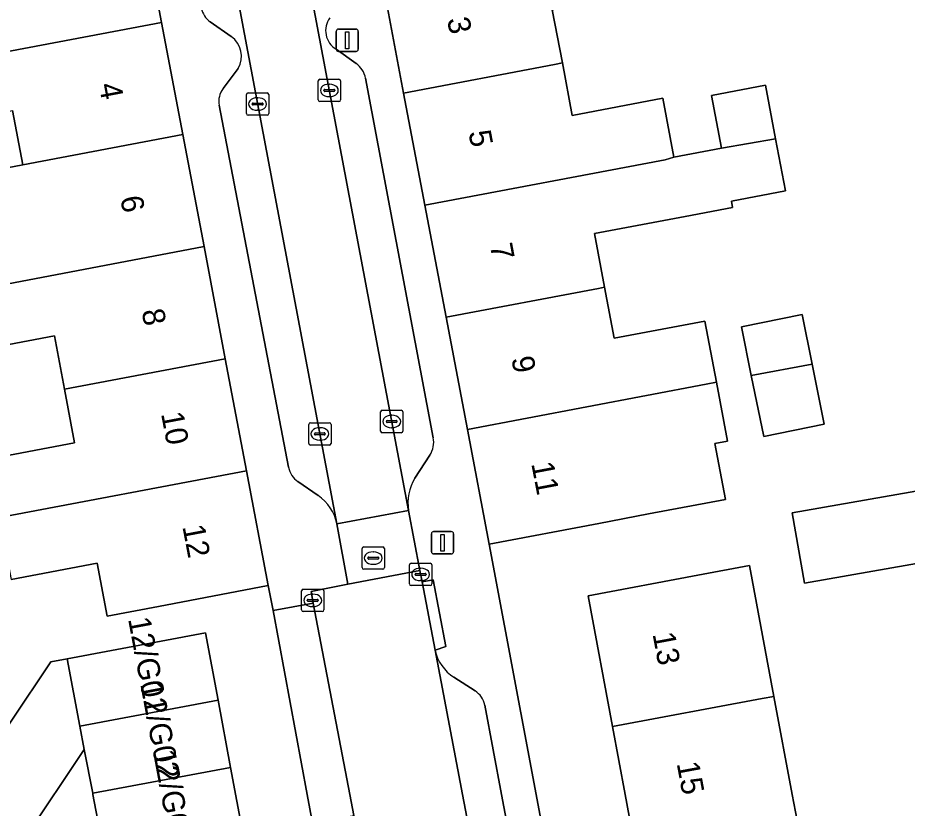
# Model space of a CAD drawing. Extents: x 158352 to 159489, y 383828 to 384603.
# Drawn here: x 158799.12 to 158838.9, y 383999.38 to 384034.72 of the extents above; entities that cross this region are included whole.
import ezdxf

# ---------------------------------------------------------------- set-up
doc = ezdxf.new("R2010")
doc.units = 0
for name, color, linetype in [('IMGEO_Erf', 7, 'Continuous'), ('IMGEO_Kolk', 7, 'Continuous'), ('IMGEO_Lichtmast', 7, 'Continuous'), ('IMGEO_Pand', 7, 'Continuous'), ('IMGEO_Pand_nummerreeks', 7, 'Continuous'), ('IMGEO_Parkeervlak_open', 7, 'Continuous'), ('IMGEO_Rijbaan_lokaal_open', 7, 'Continuous'), ('IMGEO_Rioolput', 7, 'Continuous'), ('IMGEO_Voetpad_open', 7, 'Continuous')]:
    doc.layers.add(name, color=color, linetype=linetype)

msp = doc.modelspace()

# ---------------------------------------------------------------- linework, layer by layer
at = {"layer": 'IMGEO_Erf'}
for points in [[(158823.028, 384035.085), (158823.479, 384032.704), (158823.923, 384030.362), (158827.97, 384031.129), (158828.471, 384028.487), (158830.594, 384028.89), (158830.147, 384031.248), (158832.566, 384031.706), (158833.019, 384029.317), (158833.46, 384026.99), (158831.041, 384026.532), (158831.095, 384026.248), (158828.971, 384025.846), (158824.912, 384025.077), (158825.368, 384022.673), (158825.799, 384020.396), (158829.85, 384021.163), (158830.369, 384018.427), (158830.867, 384015.798), (158830.3, 384015.691), (158830.774, 384013.189), (158827.339, 384012.538), (158825.116, 384012.116), (158820.203, 384011.185), (158822.303, 384000), (158825.129, 383984.951)], [(158796.223, 384027.56), (158799.352, 384028.152), (158798.893, 384030.579)], [(158797.802, 384014.988), (158801.665, 384015.719), (158801.211, 384018.118), (158800.76, 384020.506), (158796.907, 384019.777)], [(158812.308, 383998.709), (158812.069, 384000), (158810.545, 384008.215), (158810.321, 384009.334), (158805.409, 384008.405), (158803.118, 384007.971), (158802.67, 384010.332), (158798.821, 384009.603)], [(158826.753, 383997.491), (158826.285, 384000), (158825.719, 384003.034), (158824.629, 384008.882), (158829.545, 384009.799), (158831.854, 384010.229), (158832.942, 384004.38), (158833.757, 384000), (158833.974, 383998.837)], [(158795.269, 383997.968), (158800.605, 384005.927), (158801.324, 384006.061), (158807.522, 384007.216), (158808.082, 384004.205), (158808.642, 384001.195), (158809.202, 383998.184)], [(158803.048, 383997.036), (158802.482, 384000), (158802.473, 384000.047), (158802.097, 384002.012), (158799.476, 383998.101)]]:
    msp.add_lwpolyline(points, dxfattribs=at)
for points in [[(158834.649, 384019.239), (158835.196, 384016.556), (158832.485, 384016.003), (158831.93, 384018.723), (158831.486, 384020.901), (158834.198, 384021.454)], [(158845.956, 384014.73), (158846.506, 384011.58), (158841.025, 384010.622), (158834.309, 384009.447), (158833.758, 384012.596), (158840.474, 384013.771)]]:
    msp.add_lwpolyline(points, close=True, dxfattribs=at)
at = {"layer": 'IMGEO_Kolk'}
for p, q in [((158812.557, 384031.052), (158812.557, 384031.904)), ((158812.632, 384031.978), (158813.484, 384031.978)), ((158813.045, 384031.758), (158813.07, 384031.758)), ((158813.558, 384031.904), (158813.558, 384031.052)), ((158809.349, 384030.443), (158809.349, 384031.295)), ((158809.424, 384031.369), (158810.276, 384031.369)), ((158810.35, 384031.295), (158810.35, 384030.443)), ((158812.816, 384031.472), (158812.816, 384031.484)), ((158813.254, 384031.435), (158812.856, 384031.435)), ((158812.859, 384031.521), (158813.257, 384031.521)), ((158813.3, 384031.484), (158813.3, 384031.472)), ((158809.608, 384030.863), (158809.608, 384030.875)), ((158809.651, 384030.912), (158810.049, 384030.912)), ((158809.837, 384031.149), (158809.862, 384031.149)), ((158810.092, 384030.875), (158810.092, 384030.863)), ((158813.484, 384030.978), (158812.632, 384030.978)), ((158813.068, 384031.198), (158813.043, 384031.198)), ((158810.046, 384030.826), (158809.648, 384030.826)), ((158809.86, 384030.589), (158809.835, 384030.589)), ((158810.276, 384030.369), (158809.424, 384030.369)), ((158815.346, 384016.247), (158815.346, 384017.099)), ((158815.421, 384017.173), (158816.273, 384017.173)), ((158815.834, 384016.953), (158815.859, 384016.953)), ((158816.347, 384017.099), (158816.347, 384016.247)), ((158812.133, 384015.691), (158812.133, 384016.543)), ((158812.208, 384016.617), (158813.06, 384016.617)), ((158813.134, 384016.543), (158813.134, 384015.691)), ((158815.605, 384016.667), (158815.605, 384016.679)), ((158816.043, 384016.63), (158815.645, 384016.63)), ((158815.648, 384016.716), (158816.046, 384016.716)), ((158816.089, 384016.679), (158816.089, 384016.667)), ((158812.392, 384016.111), (158812.392, 384016.123)), ((158812.435, 384016.16), (158812.833, 384016.16)), ((158812.621, 384016.397), (158812.646, 384016.397)), ((158812.876, 384016.123), (158812.876, 384016.111)), ((158816.273, 384016.173), (158815.421, 384016.173)), ((158815.857, 384016.393), (158815.832, 384016.393)), ((158812.83, 384016.074), (158812.432, 384016.074)), ((158812.644, 384015.837), (158812.619, 384015.837)), ((158813.06, 384015.617), (158812.208, 384015.617)), ((158816.64, 384009.41), (158816.64, 384010.262)), ((158816.715, 384010.336), (158817.567, 384010.336)), ((158817.641, 384010.262), (158817.641, 384009.41)), ((158816.899, 384009.83), (158816.899, 384009.842)), ((158817.337, 384009.793), (158816.939, 384009.793)), ((158816.942, 384009.879), (158817.34, 384009.879)), ((158817.128, 384010.116), (158817.153, 384010.116)), ((158817.383, 384009.842), (158817.383, 384009.83)), ((158817.151, 384009.556), (158817.126, 384009.556)), ((158811.812, 384008.248), (158811.812, 384009.1)), ((158811.887, 384009.174), (158812.739, 384009.174)), ((158812.813, 384009.1), (158812.813, 384008.248)), ((158817.567, 384009.336), (158816.715, 384009.336)), ((158812.071, 384008.668), (158812.071, 384008.68)), ((158812.509, 384008.631), (158812.111, 384008.631)), ((158812.114, 384008.717), (158812.512, 384008.717)), ((158812.3, 384008.954), (158812.325, 384008.954)), ((158812.555, 384008.68), (158812.555, 384008.668)), ((158812.739, 384008.174), (158811.887, 384008.174)), ((158812.323, 384008.394), (158812.298, 384008.394))]:
    msp.add_line(p, q, dxfattribs=at)
for points in [[(158812.557, 384031.052), (158812.557, 384031.904)], [(158812.632, 384031.978), (158813.484, 384031.978)], [(158813.558, 384031.904), (158813.558, 384031.052)], [(158809.349, 384030.443), (158809.349, 384031.295)], [(158809.424, 384031.369), (158810.276, 384031.369)], [(158810.35, 384031.295), (158810.35, 384030.443)], [(158813.484, 384030.978), (158812.632, 384030.978)], [(158810.276, 384030.369), (158809.424, 384030.369)], [(158815.346, 384016.247), (158815.346, 384017.099)], [(158815.421, 384017.173), (158816.273, 384017.173)], [(158816.347, 384017.099), (158816.347, 384016.247)], [(158812.133, 384015.691), (158812.133, 384016.543)], [(158812.208, 384016.617), (158813.06, 384016.617)], [(158813.134, 384016.543), (158813.134, 384015.691)], [(158816.273, 384016.173), (158815.421, 384016.173)], [(158813.06, 384015.617), (158812.208, 384015.617)], [(158816.64, 384009.41), (158816.64, 384010.262)], [(158816.715, 384010.336), (158817.567, 384010.336)], [(158817.641, 384010.262), (158817.641, 384009.41)], [(158811.812, 384008.248), (158811.812, 384009.1)], [(158811.887, 384009.174), (158812.739, 384009.174)], [(158812.813, 384009.1), (158812.813, 384008.248)], [(158817.567, 384009.336), (158816.715, 384009.336)], [(158812.739, 384008.174), (158811.887, 384008.174)]]:
    msp.add_lwpolyline(points, dxfattribs=at)
for centre, radius, start, end in [((158812.634, 384031.902), 0.0765, 91.552, 178.448), ((158812.634, 384031.902), 0.0765, 91.552, 178.448), ((158813.482, 384031.902), 0.0765, 1.552, 88.448), ((158813.482, 384031.902), 0.0765, 1.552, 88.448), ((158809.426, 384031.293), 0.0765, 91.552, 178.448), ((158809.426, 384031.293), 0.0765, 91.552, 178.448), ((158810.274, 384031.293), 0.0765, 1.552, 88.448), ((158810.274, 384031.293), 0.0765, 1.552, 88.448), ((158812.856, 384031.481), 0.0403, 85.8775, 175.7526), ((158812.853, 384031.471), 0.0366, 178.938, 274.7102), ((158813.257, 384031.478), 0.043, 264.8664, 352.4533), ((158813.261, 384031.483), 0.0386, 1.7309, 96.639), ((158809.648, 384030.872), 0.0403, 85.8775, 175.7526), ((158809.645, 384030.862), 0.0366, 178.938, 274.7102), ((158810.049, 384030.869), 0.043, 264.8664, 352.4533), ((158810.053, 384030.874), 0.0386, 1.7309, 96.639), ((158812.634, 384031.054), 0.0765, 181.552, 268.448), ((158812.634, 384031.054), 0.0765, 181.552, 268.448), ((158813.482, 384031.054), 0.0765, 271.552, 358.448), ((158813.482, 384031.054), 0.0765, 271.552, 358.448), ((158809.426, 384030.445), 0.0765, 181.552, 268.448), ((158809.426, 384030.445), 0.0765, 181.552, 268.448), ((158810.274, 384030.445), 0.0765, 271.552, 358.448), ((158810.274, 384030.445), 0.0765, 271.552, 358.448), ((158815.423, 384017.097), 0.0765, 91.552, 178.448), ((158815.423, 384017.097), 0.0765, 91.552, 178.448), ((158816.271, 384017.097), 0.0765, 1.552, 88.448), ((158816.271, 384017.097), 0.0765, 1.552, 88.448), ((158812.21, 384016.541), 0.0765, 91.552, 178.448), ((158812.21, 384016.541), 0.0765, 91.552, 178.448), ((158813.058, 384016.541), 0.0765, 1.552, 88.448), ((158813.058, 384016.541), 0.0765, 1.552, 88.448), ((158815.645, 384016.676), 0.0403, 85.8775, 175.7526), ((158815.642, 384016.666), 0.0366, 178.938, 274.7102), ((158816.046, 384016.673), 0.043, 264.8664, 352.4533), ((158816.05, 384016.678), 0.0386, 1.7309, 96.639), ((158812.432, 384016.12), 0.0403, 85.8775, 175.7526), ((158812.837, 384016.122), 0.0386, 1.7309, 96.639), ((158815.423, 384016.249), 0.0765, 181.552, 268.448), ((158815.423, 384016.249), 0.0765, 181.552, 268.448), ((158816.271, 384016.249), 0.0765, 271.552, 358.448), ((158816.271, 384016.249), 0.0765, 271.552, 358.448), ((158812.429, 384016.11), 0.0366, 178.938, 274.7102), ((158812.833, 384016.117), 0.043, 264.8664, 352.4533), ((158812.21, 384015.693), 0.0765, 181.552, 268.448), ((158812.21, 384015.693), 0.0765, 181.552, 268.448), ((158813.058, 384015.693), 0.0765, 271.552, 358.448), ((158813.058, 384015.693), 0.0765, 271.552, 358.448), ((158816.717, 384010.26), 0.0765, 91.552, 178.448), ((158816.717, 384010.26), 0.0765, 91.552, 178.448), ((158817.565, 384010.26), 0.0765, 1.552, 88.448), ((158817.565, 384010.26), 0.0765, 1.552, 88.448), ((158816.939, 384009.839), 0.0403, 85.8775, 175.7526), ((158816.936, 384009.829), 0.0366, 178.938, 274.7102), ((158817.34, 384009.836), 0.043, 264.8664, 352.4533), ((158817.344, 384009.841), 0.0386, 1.7309, 96.639), ((158816.717, 384009.412), 0.0765, 181.552, 268.448), ((158816.717, 384009.412), 0.0765, 181.552, 268.448), ((158817.565, 384009.412), 0.0765, 271.552, 358.448), ((158817.565, 384009.412), 0.0765, 271.552, 358.448), ((158811.889, 384009.098), 0.0765, 91.552, 178.448), ((158811.889, 384009.098), 0.0765, 91.552, 178.448), ((158812.737, 384009.098), 0.0765, 1.552, 88.448), ((158812.737, 384009.098), 0.0765, 1.552, 88.448), ((158812.111, 384008.677), 0.0403, 85.8775, 175.7526), ((158812.108, 384008.667), 0.0366, 178.938, 274.7102), ((158812.512, 384008.674), 0.043, 264.8664, 352.4533), ((158812.516, 384008.679), 0.0386, 1.7309, 96.639), ((158811.889, 384008.25), 0.0765, 181.552, 268.448), ((158811.889, 384008.25), 0.0765, 181.552, 268.448), ((158812.737, 384008.25), 0.0765, 271.552, 358.448), ((158812.737, 384008.25), 0.0765, 271.552, 358.448)]:
    msp.add_arc(centre, radius, start, end, dxfattribs=at)
for centre, major_axis, ratio, start_param, end_param in [((158813.044, 384031.478), (-0.387, 0.002), 0.722429, 4.712389, 7.853982), ((158813.069, 384031.478), (-0.39, 0.002), 0.717154, 1.570796, 4.712389), ((158809.836, 384030.869), (-0.387, 0.002), 0.722429, 4.712389, 7.853982), ((158809.861, 384030.869), (-0.39, 0.002), 0.717154, 1.570796, 4.712389), ((158815.833, 384016.673), (-0.387, 0.002), 0.722429, 4.712389, 7.853982), ((158815.858, 384016.673), (-0.39, 0.002), 0.717154, 1.570796, 4.712389), ((158812.62, 384016.117), (-0.387, 0.002), 0.722429, 4.712389, 7.853982), ((158812.645, 384016.117), (-0.39, 0.002), 0.717154, 1.570796, 4.712389), ((158817.127, 384009.836), (-0.387, 0.002), 0.722429, 4.712389, 7.853982), ((158817.152, 384009.836), (-0.39, 0.002), 0.717154, 1.570796, 4.712389), ((158812.299, 384008.674), (-0.387, 0.002), 0.722429, 4.712389, 7.853982), ((158812.324, 384008.674), (-0.39, 0.002), 0.717154, 1.570796, 4.712389)]:
    msp.add_ellipse(centre, major_axis=major_axis, ratio=ratio, start_param=start_param, end_param=end_param, dxfattribs=at)
at = {"layer": 'IMGEO_Lichtmast'}
for p, q in [((158813.363, 384033.319), (158813.363, 384034.119)), ((158813.363, 384034.119), (158813.363, 384033.319)), ((158813.463, 384034.219), (158814.253, 384034.219)), ((158814.253, 384034.219), (158813.463, 384034.219)), ((158814.353, 384034.119), (158814.353, 384033.319)), ((158814.353, 384033.319), (158814.353, 384034.119)), ((158814.253, 384033.219), (158813.463, 384033.219)), ((158813.463, 384033.219), (158814.253, 384033.219)), ((158817.721, 384011.749), (158818.511, 384011.749)), ((158818.511, 384011.749), (158817.721, 384011.749)), ((158817.621, 384010.849), (158817.621, 384011.649)), ((158817.621, 384011.649), (158817.621, 384010.849)), ((158818.611, 384011.649), (158818.611, 384010.849)), ((158818.611, 384010.849), (158818.611, 384011.649)), ((158818.511, 384010.749), (158817.721, 384010.749)), ((158817.721, 384010.749), (158818.511, 384010.749))]:
    msp.add_line(p, q, dxfattribs=at)
for points in [[(158813.783, 384034.094), (158813.933, 384034.094), (158813.933, 384033.344), (158813.783, 384033.344), (158813.783, 384034.094)], [(158818.041, 384011.624), (158818.191, 384011.624), (158818.191, 384010.874), (158818.041, 384010.874), (158818.041, 384011.624)]]:
    msp.add_lwpolyline(points, dxfattribs=at)
for centre, start, end in [((158813.463, 384034.119), 90, 180), ((158813.463, 384034.119), 90, 180), ((158814.253, 384034.119), 0, 90), ((158814.253, 384034.119), 360, 90), ((158813.463, 384033.319), 180, 270), ((158813.463, 384033.319), 180, 270), ((158814.253, 384033.319), 270, 0), ((158814.253, 384033.319), 270, 0), ((158817.721, 384011.649), 90, 180), ((158817.721, 384011.649), 90, 180), ((158818.511, 384011.649), 0, 90), ((158818.511, 384011.649), 360, 90), ((158817.721, 384010.849), 180, 270), ((158817.721, 384010.849), 180, 270), ((158818.511, 384010.849), 270, 0), ((158818.511, 384010.849), 270, 0)]:
    msp.add_arc(centre, 0.1, start, end, dxfattribs=at)
at = {"layer": 'IMGEO_Pand'}
for points in [[(158804.584, 384039.651), (158799.672, 384038.722), (158797.627, 384038.324), (158797.504, 384038.301), (158797.444, 384038.289), (158797.871, 384036.033), (158797.913, 384035.809), (158797.973, 384035.493), (158794.092, 384034.758), (158794.532, 384032.433), (158794.797, 384032.483), (158805.555, 384034.519)], [(158816.381, 384031.359), (158823.128, 384032.637), (158823.479, 384032.704), (158823.028, 384035.085), (158827.091, 384035.855), (158826.592, 384038.488), (158826.299, 384038.432), (158815.431, 384036.372)], [(158805.555, 384034.519), (158794.797, 384032.483), (158794.532, 384032.433), (158795.021, 384029.846), (158798.893, 384030.579), (158799.352, 384028.152), (158806.504, 384029.505)], [(158816.381, 384031.359), (158817.331, 384026.345), (158828.073, 384028.38), (158828.471, 384028.487), (158827.97, 384031.129), (158823.923, 384030.362), (158823.479, 384032.704), (158823.128, 384032.637)], [(158830.594, 384028.89), (158833.019, 384029.317), (158832.566, 384031.706), (158830.147, 384031.248)], [(158807.453, 384024.492), (158806.504, 384029.505), (158799.352, 384028.152), (158796.223, 384027.56), (158796.681, 384025.138), (158795.92, 384024.994), (158796.41, 384022.402)], [(158830.594, 384028.89), (158828.471, 384028.487), (158828.073, 384028.38), (158817.331, 384026.345), (158818.281, 384021.331), (158825.101, 384022.623), (158825.368, 384022.673), (158824.912, 384025.077), (158828.971, 384025.846), (158831.095, 384026.248), (158831.041, 384026.532), (158833.46, 384026.99), (158833.019, 384029.317)], [(158801.211, 384018.118), (158808.401, 384019.479), (158807.453, 384024.492), (158796.41, 384022.402), (158796.907, 384019.777), (158800.76, 384020.506)], [(158819.231, 384016.317), (158829.912, 384018.341), (158830.369, 384018.427), (158829.85, 384021.163), (158825.799, 384020.396), (158825.368, 384022.673), (158825.101, 384022.623), (158818.281, 384021.331)], [(158831.93, 384018.723), (158834.649, 384019.239), (158834.198, 384021.454), (158831.486, 384020.901)], [(158801.211, 384018.118), (158801.665, 384015.719), (158797.802, 384014.988), (158798.297, 384012.374), (158809.35, 384014.466), (158808.401, 384019.479)], [(158831.93, 384018.723), (158832.485, 384016.003), (158835.196, 384016.556), (158834.649, 384019.239)], [(158830.867, 384015.798), (158830.369, 384018.427), (158829.912, 384018.341), (158819.231, 384016.317), (158820.203, 384011.185), (158825.116, 384012.116), (158827.339, 384012.538), (158830.774, 384013.189), (158830.3, 384015.691)], [(158809.35, 384014.466), (158798.297, 384012.374), (158798.821, 384009.603), (158802.67, 384010.332), (158803.118, 384007.971), (158805.409, 384008.405), (158810.321, 384009.334)], [(158840.474, 384013.771), (158833.758, 384012.596), (158834.309, 384009.447), (158841.025, 384010.622)], [(158832.942, 384004.38), (158831.854, 384010.229), (158829.545, 384009.799), (158824.629, 384008.882), (158825.719, 384003.034), (158832.415, 384004.282)], [(158808.082, 384004.205), (158807.522, 384007.216), (158801.324, 384006.061), (158801.898, 384003.055)], [(158802.097, 384002.012), (158801.898, 384003.055), (158801.324, 384006.061), (158800.605, 384005.927), (158795.269, 383997.968), (158795.442, 383997.878), (158795.003, 383997.224), (158797.684, 383995.427), (158799.476, 383998.101)], [(158808.082, 384004.205), (158801.898, 384003.055), (158802.097, 384002.012), (158802.473, 384000.047), (158808.642, 384001.195)], [(158826.753, 383997.491), (158833.974, 383998.837), (158833.757, 384000), (158832.942, 384004.38), (158832.415, 384004.282), (158825.719, 384003.034), (158826.285, 384000)], [(158808.642, 384001.195), (158802.473, 384000.047), (158802.482, 384000), (158803.048, 383997.036), (158809.202, 383998.184)]]:
    msp.add_lwpolyline(points, close=True, dxfattribs=at)
at = {"layer": 'IMGEO_Parkeervlak_open'}
for points in [[(158807.122, 384062.99), (158816.598, 384012.691)], [(158813.395, 384012.091), (158804.933, 384056.931)], [(158807.734, 384034.54), (158808.669, 384033.889)], [(158814.254, 384032.686), (158813.362, 384033.327)], [(158808.978, 384032.457), (158808.306, 384031.564)], [(158817.706, 384015.949), (158814.678, 384032.02)], [(158808.131, 384030.814), (158811.234, 384014.625)], [(158816.882, 384014.134), (158817.554, 384015.174)], [(158811.651, 384013.987), (158812.557, 384013.365)], [(158817.784, 384006.45), (158819.016, 384000), (158821.559, 383986.687)], [(158819.578, 384004.625), (158818.629, 384005.235)], [(158822.725, 383989.584), (158820.76, 384000), (158820.007, 384003.989)]]:
    msp.add_lwpolyline(points, dxfattribs=at)
for centre, radius, start, end in [((158808.292, 384035.344), 0.979, 190.5279, 235.2294), ((158813.855, 384034.156), 0.965, 143.8711, 239.2528), ((158808.03, 384033.002), 1.093, 330.0985, 54.2549), ((158813.633, 384031.823), 1.063, 10.6857, 54.279), ((158809.062, 384030.992), 0.948, 142.8979, 190.8341), ((158816.652, 384015.753), 1.072, 327.2813, 10.5257), ((158812.215, 384014.811), 0.999, 190.7323, 235.6053), ((158818.708, 384013.025), 2.137, 148.7367, 188.9949), ((158811.414, 384011.701), 2.019, 11.1489, 55.5226), ((158819.679, 384006.867), 1.941, 192.4051, 237.2301), ((158819.052, 384003.808), 0.972, 10.7524, 57.2491)]:
    msp.add_arc(centre, radius, start, end, dxfattribs=at)
at = {"layer": 'IMGEO_Rijbaan_lokaal_open'}
for points in [[(158807.122, 384062.99), (158803.9, 384062.38), (158804.254, 384060.511), (158804.933, 384056.931), (158813.395, 384012.091), (158816.598, 384012.691)], [(158817.107, 384010.01), (158816.598, 384012.691), (158813.395, 384012.091), (158813.89, 384009.397)]]:
    msp.add_lwpolyline(points, close=True, dxfattribs=at)
msp.add_lwpolyline([(158821.588, 383986.196), (158821.559, 383986.687), (158819.016, 384000), (158817.784, 384006.45), (158817.205, 384009.497), (158817.107, 384010.01), (158813.89, 384009.397), (158812.24, 384009.065), (158812.338, 384008.555), (158813.973, 384000), (158814.153, 383999.058), (158816.197, 383988.364)], dxfattribs=at)
at = {"layer": 'IMGEO_Rioolput'}
for p, q in [((158814.522, 384010.14), (158814.522, 384010.992)), ((158814.597, 384011.066), (158815.449, 384011.066)), ((158815.523, 384010.992), (158815.523, 384010.14)), ((158814.781, 384010.56), (158814.781, 384010.572)), ((158814.824, 384010.609), (158815.222, 384010.609)), ((158815.01, 384010.846), (158815.035, 384010.846)), ((158815.265, 384010.572), (158815.265, 384010.56)), ((158815.219, 384010.523), (158814.821, 384010.523)), ((158815.033, 384010.286), (158815.008, 384010.286)), ((158815.449, 384010.066), (158814.597, 384010.066))]:
    msp.add_line(p, q, dxfattribs=at)
for points in [[(158814.522, 384010.14), (158814.522, 384010.992)], [(158814.597, 384011.066), (158815.449, 384011.066)], [(158815.523, 384010.992), (158815.523, 384010.14)], [(158815.449, 384010.066), (158814.597, 384010.066)]]:
    msp.add_lwpolyline(points, dxfattribs=at)
for centre, radius, start, end in [((158814.599, 384010.99), 0.0765, 91.552, 178.448), ((158814.599, 384010.99), 0.0765, 91.552, 178.448), ((158815.447, 384010.99), 0.0765, 1.552, 88.448), ((158815.447, 384010.99), 0.0765, 1.552, 88.448), ((158814.821, 384010.569), 0.0403, 85.8775, 175.7526), ((158814.818, 384010.559), 0.0366, 178.938, 274.7102), ((158815.222, 384010.566), 0.043, 264.8664, 352.4533), ((158815.226, 384010.571), 0.0386, 1.7309, 96.639), ((158814.599, 384010.142), 0.0765, 181.552, 268.448), ((158814.599, 384010.142), 0.0765, 181.552, 268.448), ((158815.447, 384010.142), 0.0765, 271.552, 358.448), ((158815.447, 384010.142), 0.0765, 271.552, 358.448)]:
    msp.add_arc(centre, radius, start, end, dxfattribs=at)
for centre, major_axis, ratio, start_param, end_param in [((158815.009, 384010.566), (-0.387, 0.002), 0.722429, 4.712389, 7.853982), ((158815.034, 384010.566), (-0.39, 0.002), 0.717154, 1.570796, 4.712389)]:
    msp.add_ellipse(centre, major_axis=major_axis, ratio=ratio, start_param=start_param, end_param=end_param, dxfattribs=at)
at = {"layer": 'IMGEO_Voetpad_open'}
for points in [[(158822.303, 384000), (158820.203, 384011.185), (158819.231, 384016.317), (158818.281, 384021.331), (158817.331, 384026.345), (158816.381, 384031.359), (158815.431, 384036.372), (158814.458, 384041.506), (158814.18, 384042.98), (158811.813, 384055.528), (158810.663, 384061.723), (158809.733, 384066.626), (158806.577, 384065.871), (158807.093, 384063.116), (158807.122, 384062.99)], [(158804.933, 384056.931), (158804.254, 384060.511), (158803.9, 384062.38), (158803.354, 384065.259), (158799.884, 384064.67), (158800.802, 384059.859), (158801.964, 384053.719), (158801.638, 384053.658), (158802.965, 384046.648), (158803.273, 384045.204), (158803.565, 384045.241), (158804.584, 384039.651), (158805.555, 384034.519), (158806.504, 384029.505), (158807.453, 384024.492), (158808.401, 384019.479), (158809.35, 384014.466), (158810.321, 384009.334), (158810.545, 384008.215), (158812.338, 384008.555), (158812.24, 384009.065), (158813.89, 384009.397), (158813.395, 384012.091)], [(158808.669, 384033.889), (158807.734, 384034.54)], [(158813.362, 384033.327), (158814.254, 384032.686)], [(158808.306, 384031.564), (158808.978, 384032.457)], [(158814.678, 384032.02), (158817.706, 384015.949)], [(158811.234, 384014.625), (158808.131, 384030.814)], [(158817.554, 384015.174), (158816.882, 384014.134)], [(158812.557, 384013.365), (158811.651, 384013.987)], [(158816.598, 384012.691), (158817.107, 384010.01), (158817.205, 384009.497), (158817.696, 384009.59), (158818.262, 384006.61), (158817.784, 384006.45)], [(158818.629, 384005.235), (158819.578, 384004.625)], [(158820.007, 384003.989), (158820.76, 384000), (158822.725, 383989.584)], [(158821.559, 383986.687), (158821.588, 383986.196), (158824.65, 383984.127), (158825.129, 383984.951), (158822.303, 384000)]]:
    msp.add_lwpolyline(points, dxfattribs=at)
for points in [[(158817.205, 384009.497), (158817.784, 384006.45), (158818.262, 384006.61), (158817.696, 384009.59)], [(158812.308, 383998.709), (158814.153, 383999.058), (158813.973, 384000), (158812.338, 384008.555), (158810.545, 384008.215), (158812.069, 384000)]]:
    msp.add_lwpolyline(points, close=True, dxfattribs=at)
for centre, radius, start, end in [((158808.292, 384035.344), 0.979, 190.5279, 235.2294), ((158813.855, 384034.156), 0.965, 143.8711, 239.2528), ((158808.03, 384033.002), 1.093, 330.0985, 54.2549), ((158813.633, 384031.823), 1.063, 10.6857, 54.279), ((158809.062, 384030.992), 0.948, 142.8979, 190.8341), ((158816.652, 384015.753), 1.072, 327.2813, 10.5257), ((158812.215, 384014.811), 0.999, 190.7323, 235.6053), ((158818.708, 384013.025), 2.137, 148.7367, 188.9949), ((158811.414, 384011.701), 2.019, 11.1489, 55.5226), ((158819.679, 384006.867), 1.941, 192.4051, 237.2301), ((158819.052, 384003.808), 0.972, 10.7524, 57.2491)]:
    msp.add_arc(centre, radius, start, end, dxfattribs=at)

# ---------------------------------------------------------------- texts
at = {"layer": 'IMGEO_Pand_nummerreeks'}
for s, rotation, p in [('3', 280.7288, (158818.319, 384034.666)), ('4', 280.7141, (158802.744, 384031.733)), ('5', 280.7288, (158819.276, 384029.612)), ('6', 280.7156, (158803.7, 384026.68)), ('7', 280.7288, (158820.234, 384024.559)), ('8', 280.7156, (158804.657, 384021.623)), ('9', 280.7288, (158821.191, 384019.505)), ('10', 280.7156, (158805.527, 384017.023)), ('11', 280.7313, (158822.086, 384014.792)), ('12', 280.7156, (158806.482, 384011.976)), ('12/G01', 280.6261, (158804.052, 384007.844)), ('13', 280.5599, (158827.51, 384007.173)), ('12/G02', 280.6282, (158804.597, 384004.937)), ('12/G03', 280.6261, (158805.165, 384001.911)), ('15', 280.5599, (158828.589, 384001.385))]:
    msp.add_text(s, height=1, rotation=rotation, dxfattribs=at).set_placement(p)

doc.saveas('drawing.dxf')
